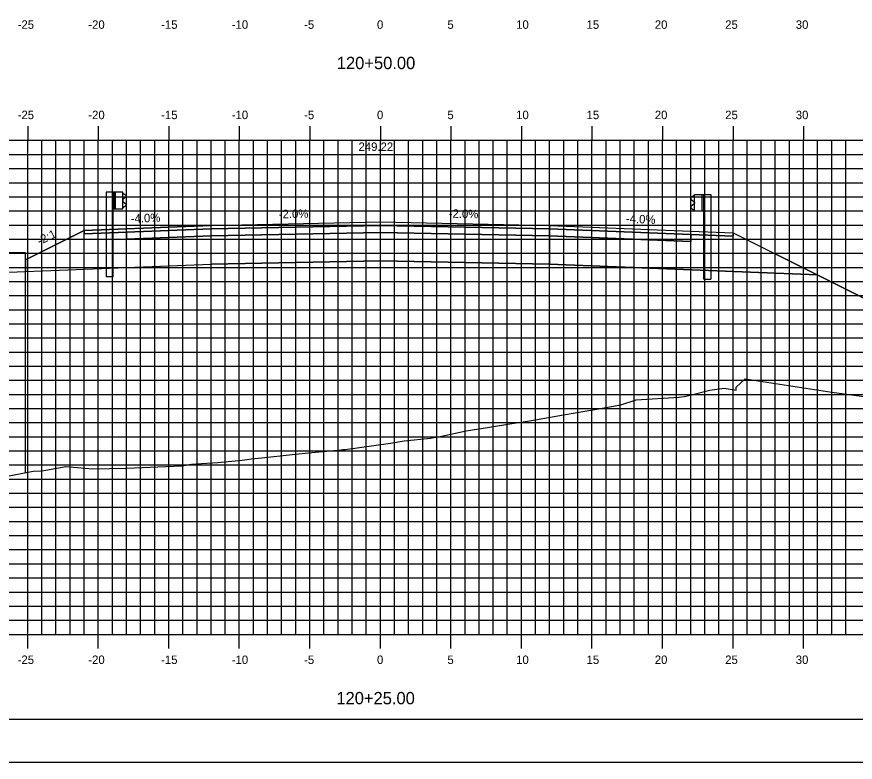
# Model space of a CAD drawing. Extents: x -22 to 1480, y -1511 to 8.
# Drawn here: x 605.9 to 665.3, y -1511.4 to -1458.6 of the extents above; entities that cross this region are included whole.
import ezdxf

# ---------------------------------------------------------------- set-up
doc = ezdxf.new("R2010")
doc.units = 0
for name, color, linetype in [('ANNOTATION', 7, 'Continuous'), ('BORDER', 7, 'Continuous'), ('D_Bridge_Wingwall', 7, 'Continuous'), ('D_Guardrail_Beam_Lt', 7, 'Continuous'), ('D_Guardrail_Beam_Rt', 7, 'Continuous'), ('D_Roadway_Centerline', 7, 'Continuous'), ('D_Roadway_Centerline_Text', 7, 'Continuous'), ('D_Roadway_Edge_Shoulder', 7, 'Continuous'), ('D_Roadway_Edge_TW', 7, 'Continuous'), ('D_Roadway_Pavement', 7, 'Continuous'), ('D_Roadway_SlopeLines', 7, 'Continuous'), ('D_Roadway_SubGrade', 7, 'Continuous'), ('H_V ANNOTATION', 7, 'Continuous'), ('MAJOR', 7, 'Continuous'), ('MINOR', 7, 'Continuous'), ('PLOT BOUNDARY', 7, 'Continuous'), ('S_Roadway_Centerline', 7, 'Continuous')]:
    doc.layers.add(name, color=color, linetype=linetype)

msp = doc.modelspace()

# ---------------------------------------------------------------- linework, layer by layer
at = {"layer": 'BORDER'}
msp.add_line((556.67, -1508.331), (716.67, -1508.331), dxfattribs=at)
at = {"layer": 'D_Bridge_Wingwall'}
msp.add_lwpolyline([(606.504, -1490.885), (606.504, -1475.297), (604.383, -1475.297), (604.383, -1491.288)], dxfattribs=at)
at = {"layer": 'D_Guardrail_Beam_Lt'}
for p, q in [((612.24, -1471.011), (612.24, -1477.011)), ((612.711, -1471.011), (612.24, -1471.011)), ((613.399, -1471.011), (612.711, -1471.011)), ((612.711, -1471.011), (612.711, -1472.178)), ((612.774, -1471.011), (612.774, -1472.178)), ((612.878, -1471.011), (612.878, -1472.178)), ((613.399, -1472.178), (613.399, -1471.011)), ((613.399, -1471.095), (613.473, -1471.109)), ((613.489, -1471.116), (613.632, -1471.216)), ((613.403, -1471.56), (613.403, -1471.63)), ((613.632, -1471.359), (613.437, -1471.495)), ((613.437, -1471.694), (613.632, -1471.83)), ((612.711, -1472.178), (613.399, -1472.178)), ((612.732, -1477.011), (612.732, -1472.178)), ((613.473, -1472.08), (613.399, -1472.095)), ((613.632, -1471.974), (613.489, -1472.074)), ((612.732, -1477.011), (612.24, -1477.011))]:
    msp.add_line(p, q, dxfattribs=at)
for centre, major_axis, start_param, end_param in [((613.465, -1471.15), (0.0417, 0), 0.959931, 1.376053), ((613.582, -1471.288), (0.0877, 0), 5.323254, 7.243116), ((613.482, -1471.56), (-0.0789, 0), 5.323254, 6.283185), ((613.482, -1471.63), (-0.0789, 0), 6.283185, 7.243116), ((613.465, -1472.04), (0.0417, 0), 4.907132, 5.323254), ((613.582, -1471.902), (0.0877, 0), 5.323254, 7.243116)]:
    msp.add_ellipse(centre, major_axis=major_axis, ratio=0.995501, start_param=start_param, end_param=end_param, dxfattribs=at)
at = {"layer": 'D_Guardrail_Beam_Rt'}
for p, q in [((653.94, -1471.171), (654.628, -1471.171)), ((653.94, -1472.338), (653.94, -1471.171)), ((654.461, -1471.171), (654.461, -1472.338)), ((654.565, -1471.171), (654.565, -1472.338)), ((654.628, -1471.171), (655.099, -1471.171)), ((654.628, -1471.171), (654.628, -1472.338)), ((655.099, -1471.171), (655.099, -1477.171)), ((653.85, -1471.276), (653.707, -1471.376)), ((653.707, -1471.519), (653.902, -1471.655)), ((653.94, -1471.255), (653.866, -1471.269)), ((653.936, -1471.72), (653.936, -1471.79)), ((653.902, -1471.854), (653.707, -1471.99)), ((653.707, -1472.134), (653.85, -1472.234)), ((653.866, -1472.24), (653.94, -1472.255)), ((654.628, -1472.338), (653.94, -1472.338)), ((654.607, -1477.171), (654.607, -1472.338)), ((654.607, -1477.171), (655.099, -1477.171))]:
    msp.add_line(p, q, dxfattribs=at)
for centre, major_axis, start_param, end_param in [((653.757, -1471.448), (-0.0877, 0), 5.323254, 7.243116), ((653.874, -1471.31), (-0.0417, 0), 4.907132, 5.323254), ((653.857, -1471.72), (0.0789, 0), 0, 0.959931), ((653.857, -1471.79), (0.0789, 0), 5.323254, 6.283185), ((653.757, -1472.062), (-0.0877, 0), 5.323254, 7.243116), ((653.874, -1472.2), (-0.0417, 0), 0.959931, 1.376053)]:
    msp.add_ellipse(centre, major_axis=major_axis, ratio=0.995501, start_param=start_param, end_param=end_param, dxfattribs=at)
at = {"layer": 'D_Roadway_Centerline'}
msp.add_lwpolyline([(606.504, -1475.797), (610.669, -1473.715), (613.669, -1473.595), (619.669, -1473.355), (631.669, -1473.115), (643.669, -1473.355), (653.669, -1473.755), (656.669, -1473.875), (662.648, -1476.864), (677.606, -1484.343), (694.963, -1493.022), (696.271, -1493.676)], dxfattribs=at)
at = {"layer": 'D_Roadway_Edge_Shoulder'}
for points in [[(619.669, -1473.355), (613.669, -1473.595), (613.669, -1473.595), (610.669, -1473.715), (610.669, -1473.965), (613.669, -1473.845), (613.669, -1473.845), (619.669, -1473.605)], [(643.669, -1473.355), (653.669, -1473.755), (653.669, -1473.755), (656.669, -1473.875), (656.669, -1474.125), (653.669, -1474.005), (653.669, -1474.005), (643.669, -1473.605)]]:
    msp.add_lwpolyline(points, close=True, dxfattribs=at)
at = {"layer": 'D_Roadway_Edge_TW'}
msp.add_lwpolyline([(619.669, -1473.605), (619.669, -1473.355), (631.669, -1473.115), (643.669, -1473.355), (643.669, -1473.605), (631.669, -1473.365)], close=True, dxfattribs=at)
at = {"layer": 'D_Roadway_Pavement'}
msp.add_lwpolyline([(619.669, -1474.105), (619.669, -1473.605), (631.669, -1473.365), (643.669, -1473.605), (643.669, -1474.105), (631.669, -1473.865)], close=True, dxfattribs=at)
for points in [[(619.669, -1473.605), (613.669, -1473.845), (613.669, -1473.845), (613.669, -1474.345), (619.669, -1474.105), (619.669, -1473.605)], [(643.669, -1473.605), (653.669, -1474.005), (653.669, -1474.005), (653.669, -1474.505), (643.669, -1474.105), (643.669, -1473.605)]]:
    msp.add_lwpolyline(points, dxfattribs=at)
at = {"layer": 'D_Roadway_SlopeLines'}
for points in [[(610.669, -1473.715), (606.504, -1475.797)], [(656.669, -1473.875), (696.271, -1493.676)], [(604.691, -1476.704), (619.669, -1476.105), (631.669, -1475.865), (643.669, -1476.105), (662.648, -1476.864)]]:
    msp.add_lwpolyline(points, dxfattribs=at)
at = {"layer": 'D_Roadway_SubGrade'}
for points in [[(619.669, -1474.105), (613.669, -1474.345), (613.669, -1473.845), (610.669, -1473.965), (610.669, -1473.715), (606.504, -1475.797), (606.504, -1476.631), (619.669, -1476.105)], [(619.669, -1476.105), (619.669, -1474.105), (631.669, -1473.865), (643.669, -1474.105), (643.669, -1476.105), (631.669, -1475.865)], [(643.669, -1474.105), (653.669, -1474.505), (653.669, -1474.005), (656.669, -1474.125), (656.669, -1473.875), (662.648, -1476.864), (643.669, -1476.105)]]:
    msp.add_lwpolyline(points, close=True, dxfattribs=at)
at = {"layer": 'MAJOR'}
for p, q in [((606.669, -1466.329), (606.669, -1467.331)), ((611.669, -1466.329), (611.669, -1467.331)), ((616.669, -1466.329), (616.669, -1467.331)), ((621.669, -1466.329), (621.669, -1467.331)), ((626.669, -1466.329), (626.669, -1467.331)), ((631.669, -1466.329), (631.669, -1467.331)), ((636.669, -1466.329), (636.669, -1467.331)), ((641.669, -1466.329), (641.669, -1467.331)), ((646.669, -1466.329), (646.669, -1467.331)), ((651.669, -1466.329), (651.669, -1467.331)), ((656.669, -1466.329), (656.669, -1467.331)), ((661.669, -1466.329), (661.669, -1467.331)), ((561.669, -1467.331), (701.669, -1467.331)), ((561.669, -1467.331), (701.669, -1467.331)), ((606.669, -1502.331), (606.669, -1467.331)), ((611.669, -1502.331), (611.669, -1467.331)), ((616.669, -1502.331), (616.669, -1467.331)), ((621.669, -1502.331), (621.669, -1467.331)), ((626.669, -1502.331), (626.669, -1467.331)), ((631.669, -1502.331), (631.669, -1467.331)), ((636.669, -1502.331), (636.669, -1467.331)), ((641.669, -1502.331), (641.669, -1467.331)), ((646.669, -1502.331), (646.669, -1467.331)), ((651.669, -1502.331), (651.669, -1467.331)), ((656.669, -1502.331), (656.669, -1467.331)), ((661.669, -1502.331), (661.669, -1467.331)), ((561.669, -1472.331), (701.669, -1472.331)), ((561.669, -1477.331), (701.669, -1477.331)), ((561.669, -1482.331), (701.669, -1482.331)), ((561.669, -1487.331), (701.669, -1487.331)), ((561.669, -1492.331), (701.669, -1492.331)), ((561.669, -1497.331), (701.669, -1497.331)), ((561.669, -1502.331), (701.669, -1502.331)), ((561.669, -1502.331), (701.669, -1502.331)), ((606.669, -1503.333), (606.669, -1502.331)), ((611.669, -1503.333), (611.669, -1502.331)), ((616.669, -1503.333), (616.669, -1502.331)), ((621.669, -1503.333), (621.669, -1502.331)), ((626.669, -1503.333), (626.669, -1502.331)), ((631.669, -1503.333), (631.669, -1502.331)), ((636.669, -1503.333), (636.669, -1502.331)), ((641.669, -1503.333), (641.669, -1502.331)), ((646.669, -1503.333), (646.669, -1502.331)), ((651.669, -1503.333), (651.669, -1502.331)), ((656.669, -1503.333), (656.669, -1502.331)), ((661.669, -1503.333), (661.669, -1502.331))]:
    msp.add_line(p, q, dxfattribs=at)
at = {"layer": 'MINOR'}
for p, q in [((607.669, -1502.331), (607.669, -1467.331)), ((608.669, -1502.331), (608.669, -1467.331)), ((609.669, -1502.331), (609.669, -1467.331)), ((610.669, -1502.331), (610.669, -1467.331)), ((612.669, -1502.331), (612.669, -1467.331)), ((613.669, -1502.331), (613.669, -1467.331)), ((614.669, -1502.331), (614.669, -1467.331)), ((615.669, -1502.331), (615.669, -1467.331)), ((617.669, -1502.331), (617.669, -1467.331)), ((618.669, -1502.331), (618.669, -1467.331)), ((619.669, -1502.331), (619.669, -1467.331)), ((620.669, -1502.331), (620.669, -1467.331)), ((622.669, -1502.331), (622.669, -1467.331)), ((623.669, -1502.331), (623.669, -1467.331)), ((624.669, -1502.331), (624.669, -1467.331)), ((625.669, -1502.331), (625.669, -1467.331)), ((627.669, -1502.331), (627.669, -1467.331)), ((628.669, -1502.331), (628.669, -1467.331)), ((629.669, -1502.331), (629.669, -1467.331)), ((630.669, -1502.331), (630.669, -1467.331)), ((632.669, -1502.331), (632.669, -1467.331)), ((633.669, -1502.331), (633.669, -1467.331)), ((634.669, -1502.331), (634.669, -1467.331)), ((635.669, -1502.331), (635.669, -1467.331)), ((637.669, -1502.331), (637.669, -1467.331)), ((638.669, -1502.331), (638.669, -1467.331)), ((639.669, -1502.331), (639.669, -1467.331)), ((640.669, -1502.331), (640.669, -1467.331)), ((642.669, -1502.331), (642.669, -1467.331)), ((643.669, -1502.331), (643.669, -1467.331)), ((644.669, -1502.331), (644.669, -1467.331)), ((645.669, -1502.331), (645.669, -1467.331)), ((647.669, -1502.331), (647.669, -1467.331)), ((648.669, -1502.331), (648.669, -1467.331)), ((649.669, -1502.331), (649.669, -1467.331)), ((650.669, -1502.331), (650.669, -1467.331)), ((652.669, -1502.331), (652.669, -1467.331)), ((653.669, -1502.331), (653.669, -1467.331)), ((654.669, -1502.331), (654.669, -1467.331)), ((655.669, -1502.331), (655.669, -1467.331)), ((657.669, -1502.331), (657.669, -1467.331)), ((658.669, -1502.331), (658.669, -1467.331)), ((659.669, -1502.331), (659.669, -1467.331)), ((660.669, -1502.331), (660.669, -1467.331)), ((662.669, -1502.331), (662.669, -1467.331)), ((663.669, -1502.331), (663.669, -1467.331)), ((664.669, -1502.331), (664.669, -1467.331)), ((561.669, -1468.331), (701.669, -1468.331)), ((561.669, -1469.331), (701.669, -1469.331)), ((561.669, -1470.331), (701.669, -1470.331)), ((561.669, -1471.331), (701.669, -1471.331)), ((561.669, -1473.331), (701.669, -1473.331)), ((561.669, -1474.331), (701.669, -1474.331)), ((561.669, -1475.331), (701.669, -1475.331)), ((561.669, -1476.331), (701.669, -1476.331)), ((561.669, -1478.331), (701.669, -1478.331)), ((561.669, -1479.331), (701.669, -1479.331)), ((561.669, -1480.331), (701.669, -1480.331)), ((561.669, -1481.331), (701.669, -1481.331)), ((561.669, -1483.331), (701.669, -1483.331)), ((561.669, -1484.331), (701.669, -1484.331)), ((561.669, -1485.331), (701.669, -1485.331)), ((561.669, -1486.331), (701.669, -1486.331)), ((561.669, -1488.331), (701.669, -1488.331)), ((561.669, -1489.331), (701.669, -1489.331)), ((561.669, -1490.331), (701.669, -1490.331)), ((561.669, -1491.331), (701.669, -1491.331)), ((561.669, -1493.331), (701.669, -1493.331)), ((561.669, -1494.331), (701.669, -1494.331)), ((561.669, -1495.331), (701.669, -1495.331)), ((561.669, -1496.331), (701.669, -1496.331)), ((561.669, -1498.331), (701.669, -1498.331)), ((561.669, -1499.331), (701.669, -1499.331)), ((561.669, -1500.331), (701.669, -1500.331)), ((561.669, -1501.331), (701.669, -1501.331))]:
    msp.add_line(p, q, dxfattribs=at)
at = {"layer": 'PLOT BOUNDARY'}
msp.add_lwpolyline([(548.576, -1511.39), (718.576, -1511.39), (718.576, -1401.39), (548.576, -1401.39)], close=True, dxfattribs=at)
at = {"layer": 'S_Roadway_Centerline'}
msp.add_lwpolyline([(599.711, -1492.176), (607.062, -1490.779), (607.699, -1490.739), (609.377, -1490.446), (611.294, -1490.593), (613.637, -1490.563), (617.592, -1490.392), (618.277, -1490.274), (618.599, -1490.254), (620.142, -1490.163), (621.87, -1489.992), (622.529, -1489.906), (623.254, -1489.837), (625.406, -1489.588), (626.819, -1489.443), (628.892, -1489.254), (628.997, -1489.241), (629.176, -1489.224), (632.384, -1488.792), (633.357, -1488.632), (635.22, -1488.422), (635.602, -1488.364), (635.8, -1488.326), (637.756, -1487.915), (639.404, -1487.642), (640.999, -1487.39), (642.11, -1487.231), (642.789, -1487.107), (644.648, -1486.775), (646.305, -1486.503), (646.861, -1486.403), (648.716, -1486.066), (649.798, -1485.718), (652.84, -1485.528), (653.21, -1485.484), (653.534, -1485.415), (655.029, -1485.029), (656.049, -1484.899), (656.889, -1485.023), (656.895, -1484.812), (657.527, -1484.222), (663.671, -1485.182), (674.536, -1486.638)], dxfattribs=at)
msp.add_lwpolyline([(599.711, -1492.176), (607.062, -1490.779), (607.699, -1490.739), (609.377, -1490.446), (611.294, -1490.593), (613.637, -1490.563), (617.592, -1490.392), (618.277, -1490.274), (618.599, -1490.254), (620.142, -1490.163), (621.87, -1489.992), (622.529, -1489.906), (623.254, -1489.837), (625.406, -1489.588), (626.819, -1489.443), (628.892, -1489.254), (628.997, -1489.241), (629.176, -1489.224), (632.384, -1488.792), (633.357, -1488.632), (635.22, -1488.422), (635.602, -1488.364), (635.8, -1488.326), (637.756, -1487.915), (639.404, -1487.642), (640.999, -1487.39), (642.11, -1487.231), (642.789, -1487.107), (644.648, -1486.775), (646.305, -1486.503), (646.861, -1486.403), (648.716, -1486.066), (649.798, -1485.718), (652.84, -1485.528), (653.21, -1485.484), (653.534, -1485.415), (655.029, -1485.029), (656.049, -1484.899), (656.889, -1485.023), (656.895, -1484.812), (657.527, -1484.222), (663.671, -1485.182), (674.536, -1486.638)], dxfattribs=at)

# ---------------------------------------------------------------- texts
at = {"layer": 'ANNOTATION'}
for s, rotation, p in [('-2.0%', 1.14576, (624.473, -1472.859)), ('-2.0%', 358.85424, (636.513, -1472.811)), ('-4.0%', 2.29061, (613.985, -1473.181)), ('-4.0%', 357.70939, (649.065, -1473.17)), ('-2:1', 26.56505, (607.516, -1474.773))]:
    msp.add_text(s, height=0.6, rotation=rotation, dxfattribs=at).set_placement(p)
at = {"layer": 'D_Roadway_Centerline'}
for s, p in [('C', (631.664, -1473.115)), ('L', (631.669, -1473.122))]:
    msp.add_text(s, height=0.0146, dxfattribs=at).set_placement(p)
at = {"layer": 'D_Roadway_Centerline_Text'}
msp.add_text('249.22', height=0.6, dxfattribs=at).set_placement((630.12, -1468.083))
at = {"layer": 'H_V ANNOTATION'}
for s, height, p in [('-25', 0.6, (605.955, -1459.431)), ('-20', 0.6, (610.963, -1459.431)), ('-15', 0.6, (616.126, -1459.431)), ('-10', 0.6, (621.134, -1459.431)), ('-5', 0.6, (626.26, -1459.431)), ('0', 0.6, (631.429, -1459.431)), ('5', 0.6, (636.421, -1459.431)), ('10', 0.6, (641.295, -1459.431)), ('15', 0.6, (646.287, -1459.431)), ('20', 0.6, (651.123, -1459.431)), ('25', 0.6, (656.115, -1459.431)), ('30', 0.6, (661.118, -1459.431)), ('120+50.00', 0.875, (628.579, -1462.288)), ('-25', 0.6, (605.955, -1465.831)), ('-20', 0.6, (610.963, -1465.831)), ('-15', 0.6, (616.126, -1465.831)), ('-10', 0.6, (621.134, -1465.831)), ('-5', 0.6, (626.26, -1465.831)), ('0', 0.6, (631.429, -1465.831)), ('5', 0.6, (636.421, -1465.831)), ('10', 0.6, (641.295, -1465.831)), ('15', 0.6, (646.287, -1465.831)), ('20', 0.6, (651.123, -1465.831)), ('25', 0.6, (656.115, -1465.831)), ('30', 0.6, (661.118, -1465.831)), ('-25', 0.6, (605.955, -1504.431)), ('-20', 0.6, (610.963, -1504.431)), ('-15', 0.6, (616.126, -1504.431)), ('-10', 0.6, (621.134, -1504.431)), ('-5', 0.6, (626.26, -1504.431)), ('0', 0.6, (631.429, -1504.431)), ('5', 0.6, (636.421, -1504.431)), ('10', 0.6, (641.295, -1504.431)), ('15', 0.6, (646.287, -1504.431)), ('20', 0.6, (651.123, -1504.431)), ('25', 0.6, (656.115, -1504.431)), ('30', 0.6, (661.118, -1504.431)), ('120+25.00', 0.875, (628.548, -1507.288))]:
    msp.add_text(s, height=height, dxfattribs=at).set_placement(p)

doc.saveas('drawing.dxf')
